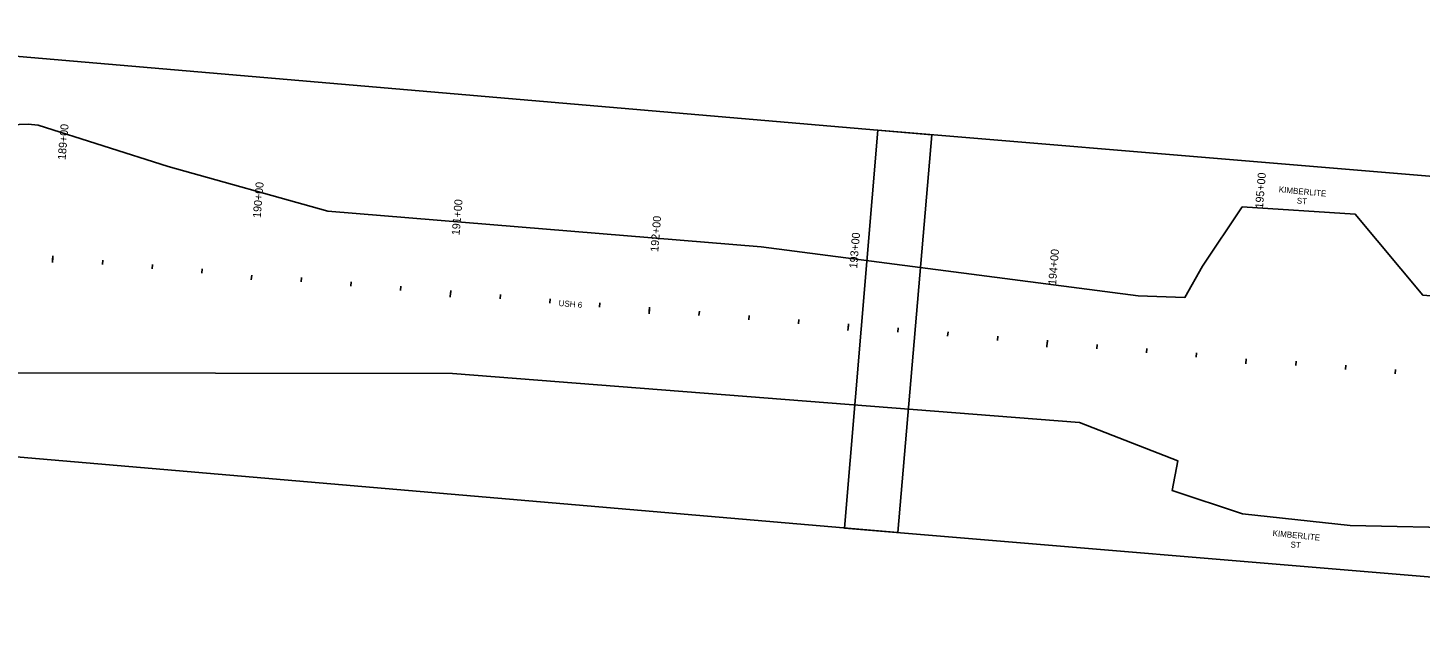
# Model space of a CAD drawing. Extents: x 20499876 to 20505320, y 7953544 to 7954108.
# Drawn here: x 20502593 to 20503290, y 7953634 to 7953937 of the extents above; entities that cross this region are included whole.
import ezdxf

# ---------------------------------------------------------------- set-up
doc = ezdxf.new("R2010")
doc.units = 0
for name, color, linetype in [('Draft_0', 7, 'Continuous'), ('Draft_7', 7, 'Continuous'), ('Drainage- Pipe', 7, 'Continuous'), ('PS_CONST', 7, 'Continuous'), ('Wall', 7, 'Continuous')]:
    doc.layers.add(name, color=color, linetype=linetype)

msp = doc.modelspace()

# ---------------------------------------------------------------- linework, layer by layer
at = {"layer": 'Draft_7'}
for p, q in [((20502605.39, 7953821.6), (20502605.18, 7953819.16)), ((20502630.19, 7953818.21), (20502630.38, 7953820.38)), ((20502655.1, 7953816.04), (20502655.28, 7953818.22)), ((20502680, 7953813.87), (20502680.19, 7953816.05)), ((20502705.01, 7953812.93), (20502704.8, 7953810.49)), ((20502729.81, 7953809.54), (20502730, 7953811.72)), ((20502754.72, 7953807.37), (20502754.91, 7953809.55)), ((20502779.62, 7953805.2), (20502779.81, 7953807.38)), ((20502804.64, 7953804.26), (20502804.42, 7953801.82)), ((20502829.44, 7953800.96), (20502829.63, 7953803.13)), ((20502854.36, 7953798.88), (20502854.54, 7953801.06)), ((20502879.27, 7953796.8), (20502879.45, 7953798.98)), ((20502904.29, 7953795.94), (20502904.08, 7953793.5)), ((20502929.1, 7953792.64), (20502929.28, 7953794.82)), ((20502954.01, 7953790.56), (20502954.19, 7953792.74)), ((20502978.92, 7953788.48), (20502979.11, 7953790.66)), ((20503003.94, 7953787.62), (20503003.74, 7953785.18)), ((20503028.75, 7953784.33), (20503028.93, 7953786.5)), ((20503053.66, 7953782.25), (20503053.85, 7953784.42)), ((20503078.58, 7953780.17), (20503078.76, 7953782.34)), ((20503103.59, 7953779.31), (20503103.39, 7953776.87)), ((20503128.4, 7953776.01), (20503128.59, 7953778.19)), ((20503153.32, 7953773.93), (20503153.5, 7953776.11)), ((20503178.23, 7953771.85), (20503178.41, 7953774.03)), ((20503203.25, 7953770.99), (20503203.04, 7953768.55)), ((20503228.06, 7953767.69), (20503228.24, 7953769.87)), ((20503252.97, 7953765.61), (20503253.15, 7953767.79)), ((20503277.89, 7953763.53), (20503278.07, 7953765.71))]:
    msp.add_line(p, q, dxfattribs=at)
at = {"layer": 'Drainage- Pipe'}
for points in [[(20502421.05, 7953936.77), (20502403.97, 7953737.5), (20503028.68, 7953683.95), (20503045.76, 7953883.22)], [(20503018.63, 7953885.52), (20503002, 7953686.21), (20503626.83, 7953634.07), (20503643.46, 7953833.37)]]:
    msp.add_lwpolyline(points, close=True, dxfattribs=at)
at = {"layer": 'PS_CONST'}
for p, q in [((20502605.28, 7953820.38), (20502605.47, 7953822.55)), ((20502705.01, 7953812.93), (20502704.8, 7953810.49)), ((20502804.53, 7953803.04), (20502804.72, 7953805.21)), ((20502904.18, 7953794.72), (20502904.37, 7953796.9)), ((20503003.84, 7953786.4), (20503004.02, 7953788.58)), ((20503103.49, 7953778.09), (20503103.67, 7953780.26)), ((20503203.25, 7953770.99), (20503203.04, 7953768.55))]:
    msp.add_line(p, q, dxfattribs=at)
at = {"layer": 'Wall'}
for points in [[(20502579.49, 7953887.98), (20502593.01, 7953888.5), (20502597.99, 7953888.06), (20502663.24, 7953867.31), (20502743.17, 7953845.01), (20502960.26, 7953827.03), (20503149.04, 7953802.5), (20503172.51, 7953801.74), (20503181.34, 7953817.32), (20503201.28, 7953847.18), (20503257.87, 7953843.36), (20503291.71, 7953802.91), (20503646.48, 7953772.26), (20503829.09, 7953744.97), (20504079.02, 7953722.08)], [(20503994.1, 7953676.75), (20503832.88, 7953690.55), (20503683.62, 7953704.36), (20503365.12, 7953730.13), (20503318.98, 7953693.96), (20503318.32, 7953686.11), (20503255.28, 7953687.43), (20503201.41, 7953693.27), (20503166.1, 7953705.05), (20503168.96, 7953719.94), (20503119.74, 7953739.09), (20502805.68, 7953763.59), (20502567.99, 7953764)]]:
    msp.add_lwpolyline(points, dxfattribs=at)

# ---------------------------------------------------------------- texts
at = {"layer": 'Draft_0'}
for s, rotation, p in [('KIMBERLITE', 354.89018, (20503219.47, 7953854.36)), ('ST', 354.89018, (20503228.48, 7953848.74)), ('USH 6', 355, (20502858.68, 7953797.46)), ('KIMBERLITE', 354.31767, (20503216.36, 7953682.27)), ('ST', 354.31767, (20503225.32, 7953676.55))]:
    msp.add_text(s, height=3, rotation=rotation, dxfattribs=at).set_placement(p)
at = {"layer": 'Draft_7'}
for s, rotation, p in [('189+00', 85.02642, (20502611.76, 7953870.48)), ('195+00', 85.22957, (20503211.63, 7953846.14)), ('190+00', 85.02642, (20502709.5, 7953841.42)), ('191+00', 85.02642, (20502809.13, 7953832.75)), ('192+00', 85.22957, (20502908.68, 7953824.45)), ('193+00', 85.22957, (20503008.33, 7953816.13)), ('194+00', 85.22957, (20503107.98, 7953807.82))]:
    msp.add_text(s, height=4.008, rotation=rotation, dxfattribs=at).set_placement(p)
at = {"layer": 'PS_CONST'}
msp.add_text('190+00', height=4.008, rotation=85.02642, dxfattribs=at).set_placement((20502709.5, 7953841.42))

doc.saveas('drawing.dxf')
